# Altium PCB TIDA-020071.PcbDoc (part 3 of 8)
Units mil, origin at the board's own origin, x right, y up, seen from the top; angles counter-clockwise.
Board outline 5750 x 4050 mil, 6 copper layers (Top Layer, GND PLANE-1, SIGNAL LAYER, SIGNAL/POWER LAYER, GND PLANE-2, Bottom Layer), stack 59.616 mil thick; 776 components, 498 nets, 2205 pads, 871 vias.
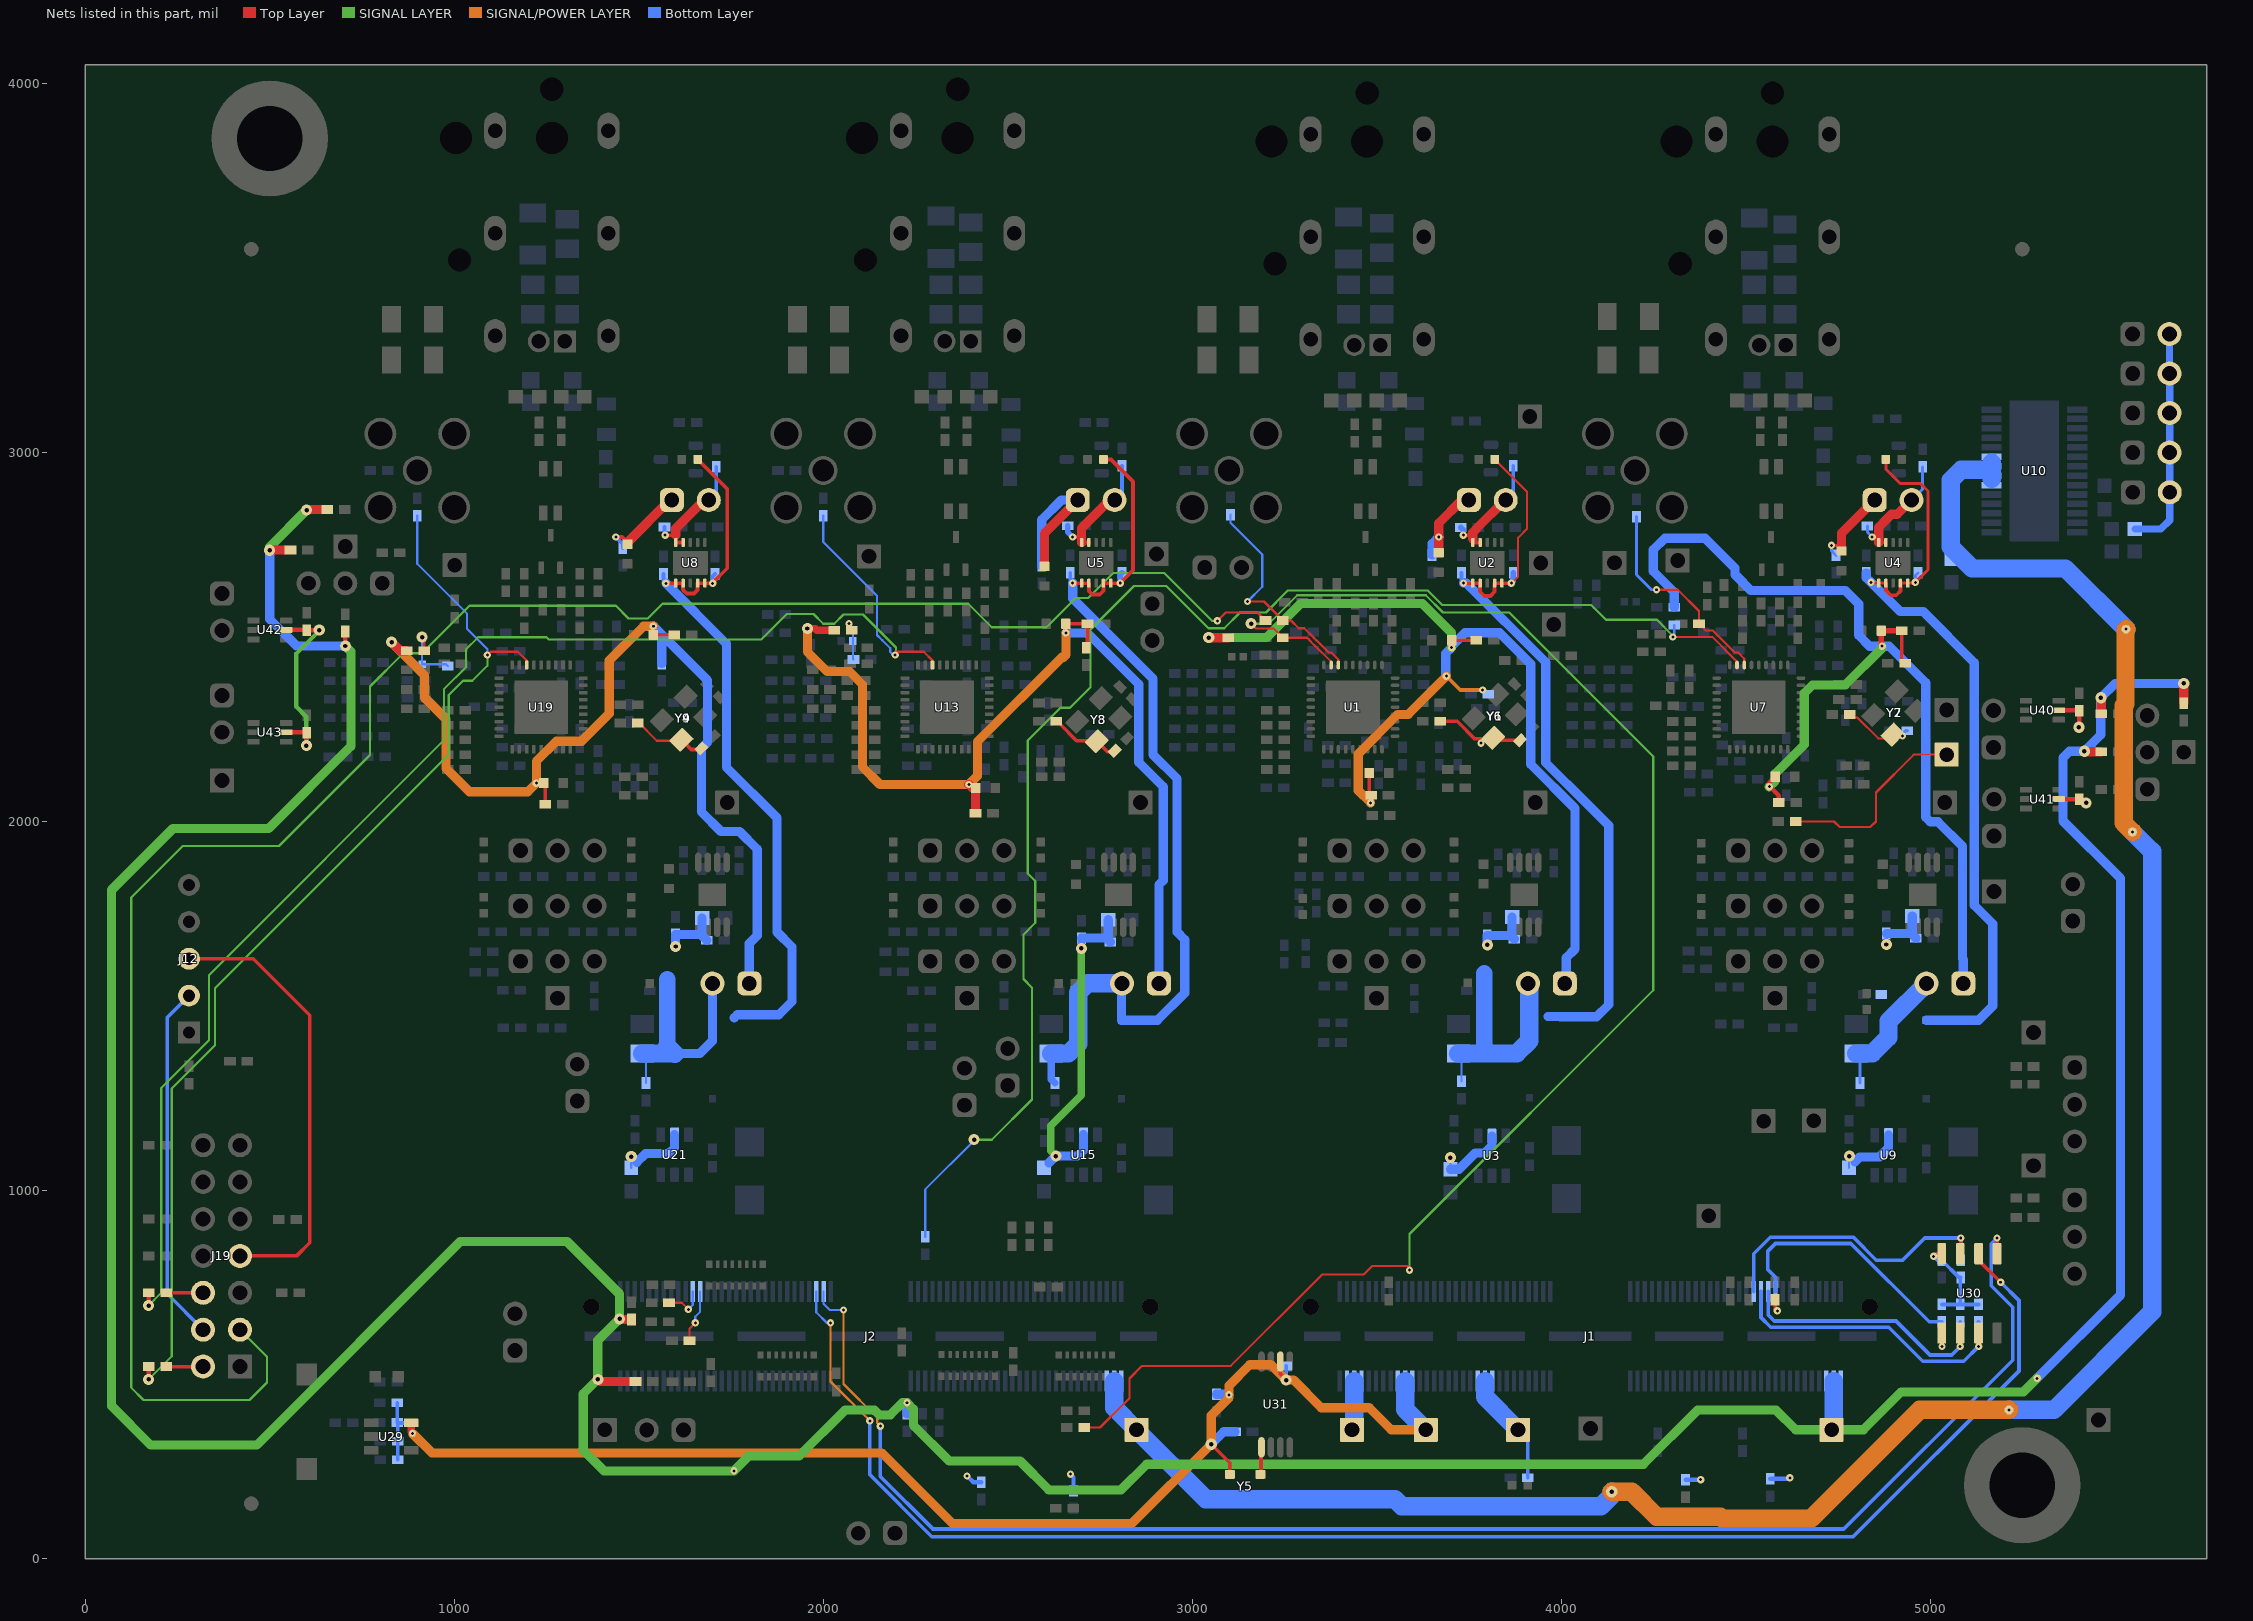
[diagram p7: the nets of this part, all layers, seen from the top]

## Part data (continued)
R11 R64 R117 R170: library part CMP-0026298-2, "RES, 33.2 k, 1%, 0.063 W, AEC-Q200 Grade 0, 0402", Manufacturer=Vishay-Dale, Power_W=63mW, Supplier Part Number 1=541-33.2KLCT-ND, TempCo="100 ppm/C", Tolerance_%=1%, Value2=0.063W, Value_Code=33k2, ValueDisplayed=33.2k
R13 R66: library part CMP-0026952-5, "RES, 5.6 k, 5%, 0.063 W, AEC-Q200 Grade 0, 0402", Manufacturer=Vishay-Dale, Power_W=63mW, Supplier Part Number 1=541-5.6KJCT-ND, TempCo="200 ppm/C", Tolerance_%=5%, Value2=0.063W, Value_Code=5k60, ValueDisplayed=5.6k
R14 R67: library part CMP-0026027-3, "RES, 15.0 k, 1%, 0.063 W, AEC-Q200 Grade 0, 0402", Manufacturer=Vishay-Dale, Power_W=63mW, Supplier Part Number 1=541-15.0KLCT-ND, TempCo="100 ppm/C", Tolerance_%=1%, Value2=0.063W, Value_Code=15k0, ValueDisplayed=15.0k
R15 R18 R19 R22 R29 R30 R31 R32 R33 R34 R35 R36 R37 R38 R68 R71 R72 R75 R82 R83 R84 R85 R86 R87 R89 R90 R91 R121 R124 R125 R128 R135 R136 R137 R138 R139 R140 R142 R143 R144 R174 R177 R178 R181 R188 R189 R190 R191 R192 R193 R194 R195 R197 R341 R342 R343 R344 R345 R346 R370 R371 R373 R374 R375 R378 R379 R381 R382 R383 R386 R387 R388 R389 R391: library part CMP-0026237-2, "RES, 2.49 k, 1%, 0.063 W, AEC-Q200 Grade 0, 0402", Manufacturer=Vishay-Dale, Power_W=63mW, Supplier Part Number 1=541-2.49KLCT-ND, TempCo="100 ppm/C", Tolerance_%=1%, Value2=0.063W, Value_Code=2k49
R16 R17 R20 R21 R23 R23-2 R25 R26 R27 R28 R48 R49 R69 R70 R73 R74 R76 R76-2 R78 R79 R80 R101 R102 R122 R123 R126 R127 R129 R129-2 R131 R132 R133 R154 R155 R175 R176 R179 R180 R182 R182-2 R184 R185 R186 R207 R208 R264 R265 R266 R267 R268 R306 R312 R315 R318 R321 R323: library part CMP-0026890-5, "RES, 2.2 k, 5%, 0.063 W, AEC-Q200 Grade 0, 0402", Manufacturer=Vishay-Dale, Power_W=63mW, Supplier Part Number 1=541-2.2KJCT-ND, TempCo="200 ppm/C", Tolerance_%=5%, Value2=0.063W, Value_Code=2k20, ValueDisplayed=2k2
R23-1 R76-1 R129-1 R182-1 R275 R276 R277 R278 R307 R309 R310 R313: library part CMP-0025958-1, "RES, 10.0 k, 1%, 0.063 W, 0402", Manufacturer=Vishay-Dale, Power_W=63mW, Supplier Part Number 1=541-10.0KLCT-ND, TempCo="100 ppm/C", Tolerance_%=1%, Value2=0.063W, Value_Code=10k0, ValueDisplayed=10.0k
R24 R77 R81 R111 R114 R115 R130 R134 R151 R164 R217 R271 R272 R273 R274 R280 R282 R330 R331 R332 R333 R340 R347 R348 R361 R365 R367 R376 R400 R404 R408 R409 R410 R411 R412 R413 R414 R415 R416 R417 R418: library part CMP-0026992-3, "RES, 0, 5%, 0.1 W, AEC-Q200 Grade 0, 0402", Manufacturer=Panasonic, Power_W=100mW, Supplier Part Number 1=P0.0JCT-ND, TempCo="600 ppm/C", Tolerance_%=5%, Value2=0.1W, Value_Code=0000, ValueDisplayed=0
R58: library part CMP-0026992-3, "RES, 0, 5%, 0.1 W, AEC-Q200 Grade 0, 0402", Manufacturer=Panasonic, Power_W=100mW, Supplier Part Number 1=P0.0JCT-ND, TempCo="600 ppm/C", Tolerance_%=5%, Value2=0.1W, Value_Code=0000
R59 R112 R165 R218: library part CMP-0025951-3, "RES, 100, 1%, 0.063 W, AEC-Q200 Grade 0, 0402", Manufacturer=Vishay-Dale, Power_W=63mW, Supplier Part Number 1=541-100LCT-ND, TempCo="100 ppm/C", Tolerance_%=1%, Value2=0.063W, Value_Code=100R, ValueDisplayed=100
R60 R61 R113 R166 R167 R219: library part CMP-0026071-3, "RES, 1.00 k, 1%, 0.063 W, AEC-Q200 Grade 0, 0402", Manufacturer=Vishay-Dale, Power_W=63mW, Supplier Part Number 1=541-1.00KLCT-ND, TempCo="100 ppm/C", Tolerance_%=1%, Value2=0.063W, Value_Code=1k00, ValueDisplayed=1k0
R88 R196 R372 R390: library part CMP-0078669-1, "RES, 10.0 k, 1%, 0.063 W, 0402", Manufacturer="Yageo America", Power_W=63mW, Supplier Part Number 1=311-10.0KLRCT-ND, TempCo="100 ppm/C", Tolerance_%=1%, Value2=0.063W, Value_Code=10k0, ValueDisplayed=10k
R98 R269 R308 R311 R324: library part CMP-0026816-1, "RES, 2.00 k, 0.1%, 0.063 W, 0402", Manufacturer="Susumu Co Ltd", Power_W=63mW, Supplier Part Number 1=RG10P2.0KBCT-ND, TempCo="25 ppm/C", Tolerance_%=0.1%, Value2=0.063W, Value_Code=2k00, ValueDisplayed=2k0
R119 R172: library part CMP-0026076-3, "RES, 1.13 k, 1%, 0.063 W, AEC-Q200 Grade 0, 0402", Manufacturer=Vishay-Dale, Power_W=63mW, Supplier Part Number 1=541-1.13KLCT-ND, TempCo="100 ppm/C", Tolerance_%=1%, Value2=0.063W, Value_Code=1k13, ValueDisplayed=1.13k
R120 R173: library part CMP-0026410-2, "RES, 4.53 k, 1%, 0.063 W, AEC-Q200 Grade 0, 0402", Manufacturer=Vishay-Dale, Power_W=63mW, Supplier Part Number 1=541-4.53KLCT-ND, TempCo="100 ppm/C", Tolerance_%=1%, Value2=0.063W, Value_Code=4k53, ValueDisplayed=4.53k
R141: library part CMP-0026739-1, "RES, 4.70 k, 1%, 0.0625 W, 0402", Manufacturer="Yageo America", Power_W=62.5mW, Supplier Part Number 1=311-4.7KLRCT-ND, TempCo="100 ppm/C", Tolerance_%=1%, Value2=0.0625W, Value_Code=4k70, ValueDisplayed=4k7
R168 R183 R187 R204: library part CMP-0089632-1, "0 Ohms Jumper 0.125W, 1/8W Chip Resistor 0805 (2012 Metric) Automotive AEC-Q200 Thick Film", Digikey Part Number=RMCF0805ZT0R00CT-ND, Manufacturer="Stackpole Electronics", Operating Temperature Range="-55°C to +155°C", Power_W=125mW, TempCo=200ppm/°C
R220 R229: library part CMP-0021998-4, "RES, 10.0 k, 1%, 0.1 W, AEC-Q200 Grade 0, 0603", Manufacturer=Vishay-Dale, Power_W=100mW, Supplier Part Number 1=541-10.0KHCT-ND, TempCo="100 ppm/C", Tolerance_%=1%, Value2=0.1W, Value_Code=10k0, ValueDisplayed=10.0k
R223 R224 R234 R235 R245 R246 R253 R254: library part CMP-0026210-2, "RES, 26.7, 1%, 0.063 W, AEC-Q200 Grade 0, 0402", Manufacturer=Vishay-Dale, Power_W=63mW, Supplier Part Number 1=541-26.7LCT-ND, TempCo="100 ppm/C", Tolerance_%=1%, Value2=0.063W, Value_Code=26R7
R225 R226 R236 R237 R247 R248 R255 R256: library part CMP-0021848-2, "RES, 1.00 k, 1%, 0.25 W, 0805", Manufacturer=Panasonic, Power_W=250mW, Supplier Part Number 1=P16058CT-ND, TempCo="100 ppm/C", Tolerance_%=1%, Value2=0.25W, Value_Code=1k00, ValueDisplayed=1k0
R227 R238 R249 R257: library part CMP-0020834-3, "RES, 100 k, 1%, 0.125 W, AEC-Q200 Grade 0, 0805", Manufacturer=Vishay-Dale, Power_W=125mW, Supplier Part Number 1=541-100KCCT-ND, TempCo="100 ppm/C", Tolerance_%=1%, Value2=0.125W, Value_Code=100k
R228 R239 R250 R258: library part CMP-0018610-3, "RES, 1.0 M, 5%, 0.25 W, AEC-Q200 Grade 0, 1206", Manufacturer=Vishay-Dale, Power_W=250mW, Supplier Part Number 1=541-1.0MECT-ND, TempCo="200 ppm/C", Tolerance_%=5%, Value2=0.25W, Value_Code=1M00, ValueDisplayed=1M
R230: library part CMP-0025797-4, "RES, 3.3 k, 5%, 0.1 W, AEC-Q200 Grade 0, 0603", Manufacturer=Vishay-Dale, Power_W=100mW, Supplier Part Number 1=541-3.3KGCT-ND, TempCo="200 ppm/C", Tolerance_%=5%, Value2=0.1W, Value_Code=3k30, ValueDisplayed=3.3k
R259: library part CMP-0074667-1, "RES, 2.20 k, 0.1%, 0.0625 W, AEC-Q200 Grade 0, 0402", Manufacturer=Panasonic, Power_W=62.5mW, Supplier Part Number 1=P2.2KDCCT-ND, TempCo="25 ppm/C", Tolerance_%=0.1%, Value2=0.0625W, Value_Code=2k20, ValueDisplayed=2k2
R260: library part CMP-0026660-1, "RES, 1.00 M, 1%, 0.1 W, 0402", Manufacturer=Panasonic, Power_W=100mW, Supplier Part Number 1=P1.00MLCT-ND, TempCo="100 ppm/C", Tolerance_%=1%, Value2=0.1W, Value_Code=1M00, ValueDisplayed=1M
R262: library part CMP-0026736-1, "RES, 470, 1%, 0.063 W, 0402", Manufacturer="Yageo America", Power_W=63mW, Supplier Part Number 1=311-470LRCT-ND, TempCo="100 ppm/C", Tolerance_%=1%, Value2=0.063W, Value_Code=470R, ValueDisplayed=470
R279 R281: library part CMP-0026992-3, "RES, 10.0 k, 1%, 0.1 W, 0402", Manufacturer=Panasonic, PartNumber=ERJ-2GE0R00X, Power_W=100mW, Supplier Part Number 1=P0.0JCT-ND, TempCo="600 ppm/C", Tolerance_%=5%, Value2=0.1W, Value_Code=0000, ValueDisplayed=10k
R380: library part CMP-0026237-2, "RES, 2.49 k, 1%, 0.063 W, AEC-Q200 Grade 0, 0402", Manufacturer=Vishay-Dale, Power_W=63mW, Supplier Part Number 1=541-2.49KLCT-ND, TempCo="100 ppm/C", Tolerance_%=1%, Value2=0.063W, Value_Code=2k49, ValueDisplayed=2.49k
RN1 RN2 RN3 RN4: library part CMP-0015352-2, "RES, 0, 5%, 0.0625 W, Resistor Array - 8x1", Manufacturer=Panasonic, Power_W=62.5mW, Supplier Part Number 1=Y1000CT-ND, TempCo=ppm/C, Tolerance_%=5%, Value2=0.0625W, Value_Code=0000, ValueDisplayed=0
S1: library part CMP-0002170-2, "Switch, Normally open, 2.3N force, 200k operations, SMD", CurrentRating_mA=1.001kA, Manufacturer="C&K Components"
U1 U7: library part CMP-0085268-1, "Low Power Auto PHY 1000BASE-T1 Automotive Ethernet Physical Layer Transceiver, RND0036A (VQFNP-36)", Alternate Manufacturer="Texas Instruments", Alternate PartNumber=DP83TG720SWRNDTQ1, PartNumber=DP83TG721-Q1
U2 U4 U5 U8: library part CMP-0036364-1, "Single Output Automotive LDO, 500 mA, Adjustable 0.8 to 3.6 V Output, 0.8 to 5.5 V Input, with Programmable Soft Start, 10-pin SON (DRC), -40 to 125 degC, Green (RoHS & no Sb/Br)", Manufacturer="Texas Instruments", Rating=Automotive
U3 U9 U15 U21: library part CMP-0076377-2, "SIMPLE SWITCHER(R) 4.5V to 42V, 0.6A Step-Down DC/DC Switching Regulator in SOT-23 Package, DDC0006A (SOT-23-T-6)", Alternate Manufacturer="Texas Instruments", Alternate PartNumber=LMR14206XMKE/NOPB
U6 U12 U18 U24: library part CMP-0013312-4, "300mA High-Voltage Ultra-Low-Iq Low-Dropout (LDO) Regulator, DGN0008D (VSSOP-8)", Alternate Manufacturer="Texas Instruments"
U10: library part CMP-0073696-3, "40-V/160-mohm Quad Channels Smart High-Side Switch, PWP0028C (TSSOP-28)", Alternate Manufacturer="Texas Instruments"
U13 U19: library part CMP-0089064-1, "TC-10 Compliant 100Base-T1 Automotive Ethernet PHY", Manufacturer="Texas Instruments", Operating Temperature Range="-40°C to +125°C", PartNumber=DP83TC818-Q1
U25 U26 U27 U28: library part CMP-0073595-1, "Automotive Dual-Channel High-Speed ESD Protection Device, DCK0003A (SOT-SC70-3)", Alternate Manufacturer="Texas Instruments"
U29: library part CMP-0074267-1, "Nanopower Supervisory Circuits for Automotive, DBV0005A (SOT-23-5)", Alternate Manufacturer="Texas Instruments"
U30: library part CMP-0005313-2, "256 kb I2C CMOS Serial EEPROM, SOIC-8", Manufacturer="ON Semiconductor", Supplier Part Number 1=CAT24C256WI-GT3OSCT-ND
U31: library part CMP-0860874-2, "3.3-V and 2.5-V LVCMOS High-Performance Clock Buffer Family, PW0008A (TSSOP-8)", Alternate Manufacturer="Texas Instruments", Alternate PartNumber=LMK1C1104PWR
U40 U41 U42 U43: library part CMP-0860319-1, "1-ch, 2:1 general-purpose analog multiplexer with 1.8-V logic control, DCK0006A (SOT-SC70-6)", Alternate Manufacturer="Texas Instruments", Operating Temperature Range="-40 to 125 C", Rating=Catalog
Y1 Y2 Y3 Y4: library part CMP-0004682-5, "Crystal, 25 MHz, 12pF, AEC-Q200 Grade 1, SMD", Frequency_Fixed=25MHz, Frequency Stability="50 ppm", Load Capacitance="12 pF", Manufacturer="Abracon Corporation"
Y5 Y6 Y7 Y8 Y9: library part CMP-0001498-1, "Low Jitter, Low Power, LVCMOS Output, BAW Oscillator", Frequency Stability=20ppm, Frequency_Fixed=25MHz, Manufacturer="Texas Instruments", Max Supply Current=5mA, Max Supply Voltage=3.63V, Min Supply Voltage=1.62V, Operating Temperature Range="-40°C to +125°C"
ZZ1: library part CMP-0003616-3
ZZ2: library part CMP-0077236-1
ZZ3: library part CMP-0077237-1
ZZ4: library part CMP-0077238-1

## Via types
v1: diameter 20, hole 8, Top Layer to Bottom Layer, tented both sides, 637 vias
v2: diameter 30, hole 12, Top Layer to Bottom Layer, tented both sides, 105 vias
v3: diameter 19.68, hole 7.87, Top Layer to Bottom Layer, tented bottom, 68 vias
v4: diameter 19.68, hole 7.87, Top Layer to Bottom Layer, 25 vias
v5: diameter 24, hole 8, Top Layer to Bottom Layer, tented both sides, 24 vias
v6: diameter 19.68, hole 7.87, Top Layer to Bottom Layer, tented both sides, 12 vias

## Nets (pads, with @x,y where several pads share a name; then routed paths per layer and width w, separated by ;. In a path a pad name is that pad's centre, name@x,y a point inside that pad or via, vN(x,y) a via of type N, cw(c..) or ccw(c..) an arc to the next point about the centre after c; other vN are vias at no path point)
1V8: 1V8.1 J1.114 J1.116 J1.118 | length 134.5
  Bottom Layer w50: 1V8.1@3433.27,350 3439.37,356.1 J1.116@3439.37,482.01
3V3: 3V3.1 J1.2 J1.4 J1.6 R98.1 R268.2 R306.1 R308.2 R309.1 R311.2 R312.2 R313.1 R324.1 | length 12482.3
  Top Layer w12: v2(705,2474.38) R98.1@705,2513.65
  Top Layer w25: v2(499.95,2733.98) 500.61,2734.65 R311.2@556.32,2734.65 ; v2@599.37,2842.31 601.24,2844.17 R313.1@655.75,2844.17 ; v2(1389.35,487) 1395.06,481.28 R312.2@1491.38,481.28 ; v2(1448.2,650.9) 1450.17,648.93 R268.2@1480.68,648.93 ; v2(5418.35,2189.14) 5419.69,2187.79 R324.1@5464.24,2187.79 ; v2(5462.86,2334.14) 5464.24,2332.76 R308.2@5464.24,2290.63 ; R309.1@5687.51,2319.63 v2(5687.51,2372.91)
  SIGNAL LAYER w25: v2(499.95,2733.98) 499.95,2742.88 v2(599.97,2842.91) ; v2(705,2474.38) 720,2459.38 720,2202.84 497.06,1979.9 238.14,1979.9 71.41,1813.17 71.41,414.93 177.63,308.71 464.53,308.71 1016.52,860.7 1305.72,860.7 1448.2,718.22 v2(1448.2,650.9) 1389.35,592.05 v2(1389.35,487) 1350,447.65 1350,295 1406.18,238.82 v1(1758.27,238.82) 1799.07,279.62 1935.43,279.62 2059.8,404 2138.94,404 2152.44,390.5 2182.22,390.5 2215.22,423.5 v1(2227.24,423.5) 2244.51,406.24 2244.51,362.85 2341.95,265.41 2533.66,265.41 2611.71,187.36 2807.43,187.36 2877.07,257.01 4223.1,257.01 4369.65,403.55 4582.57,403.55 4636.12,350 3V3.1@4733.27,350 4819.29,350 4922.19,452.9 5253.16,452.9 v1(5290,489.74)
  Bottom Layer w25: v2(499.95,2733.98) 499.95,2547.36 572.92,2474.38 v2(705,2474.38) ; R306.1@2227.24,393.62 v1(2227.24,423.5) ; v1(5290,489.74) 5515.89,715.62 5515.89,1844.61 5360.3,2000.2 5360.3,2171.34 5378.1,2189.14 v2(5418.35,2189.14) 5462.86,2233.65 v2(5462.86,2334.14) 5501.64,2372.91 v2(5687.51,2372.91)
  Bottom Layer w50: 3V3.1@4733.27,350 4738.58,355.31 J1.4@4738.58,482.01
3V3IO: 3V3IO.1 C175.1 C177.1 C178.1 J1.100 J1.102 J1.104 R259.2 R260.1 R262.2 R269.2 U29.5 U31.6 Y5.4 | length 3877.3
  Top Layer w10: v2(3051.77,311.04) 3102.22,260.59 Y5.4@3102.22,229.29 ; U31.6@3239.2,534.99 3239.2,500.8 v2(3255,485)
  Top Layer w20: U29.5@883.27,369.16 883.27,344.17 v1(887.1,340.34)
  SIGNAL/POWER LAYER w25: v1(887.1,340.34) 939.82,287.62 2159.09,287.62 2350.25,96.45 2837.19,96.45 v2(3051.77,311.04) 3051.77,388.73 3100,436.96 v1(3100,445) 3100,469.78 3099.89,469.89 3156.31,526.31 3213.69,526.31 v2(3255,485) 3275,485 3350,410 3479.8,410 3539.8,350 3V3IO.1@3633.27,350
  Bottom Layer w10: R262.2@845.87,423.09 R260.1@845.87,369.76 R260.1@847.24,368.39 ; R259.2@847.24,269.09 C175.1@847.24,319.09 R260.1@847.24,368.39 ; v1(887.1,340.34) 887.1,359.8 878.51,368.39 R260.1@847.24,368.39 ; v2(3255,485) 3255.24,484.76 C177.1@3255.24,523.03
  Bottom Layer w25: v2(3051.77,311.04) 3085.73,345 R269.2@3116.38,345 ; C178.1@3066.15,446.72 3098.28,446.72 v1(3100,445)
  Bottom Layer w50: J1.102@3577.17,482.01 3577.17,406.1 3V3IO.1@3633.27,350
5V0: 5V0.1 C2.1 C25.1 C26.1 C36.1 C59.1 C60.1 C70.1 C93.1 C94.1 C104.1 C127.1 C128.1 C176.2 C200.2 C201.2 C202.2 C203.2 J1.78 J1.80 J1.82 J25.2 J26.2 J27.2 J33.2 J34.2 R10.2 R28.2 R44.2 R63.2 R97.2 R116.2 R150.2 R169.2 R203.2 R229.1 R264.2 R265.2 R266.2 R267.2 U3.5 U9.5 U15.5 U21.5 U30.8 U40.2 U41.2 U42.2 U43.2 | length 4083.2
  Top Layer w10: v2@4880,1663.78 v2(4881.61,1665.39) ; v1(5009.85,820) 5017.17,827.32 U30.8@5031.5,827.32
  Top Layer w12: U43.2@544.74,2240.5 599.33,2240.5 C203.2@600.45,2239.39 599.33,2238.28 v2(599.33,2204.6) ; U42.2@544.74,2517.9 599.86,2517.9 C202.2@600.45,2517.31 v2(634.32,2517.31) ; U41.2@5348.69,2059.49 5403.81,2059.49 C201.2@5404.4,2058.9 5413.1,2058.9 v2(5422.9,2049.1) ; U40.2@5348.69,2300.42 5403.28,2300.42 C200.2@5404.4,2299.31 5404.4,2255.19 v2(5403.35,2254.14)
  SIGNAL LAYER w12: v2(599.33,2204.6) 599.33,2282.7 572.45,2309.59 572.45,2454.08 635,2516.63 v2(634.32,2517.31)
  SIGNAL LAYER w20: v2(2630.6,1092.11) 2617,1105.71 2617,1174.3 2700,1257.3 v2(2700,1655.01)
  Bottom Layer w6: v2(1479.83,1090.5) 1480,1090.33 C104.1@1480,1060 ; C2.1@3700,1056.42 3700,1087.64 v2(3700.06,1087.7) ; C36.1@4780,1060 4780,1090.93 v2(4781.18,1092.11)
  Bottom Layer w10: v1(2670.54,230) 2678.58,221.95 R116.2@2678.58,184.86 ; 5V0.1@3883.27,350 3910,323.27 R28.2@3910,220 ; v2(4881.61,1665.39) R97.2@4881.61,1695.16 ; v1(5009.85,820) 5019.85,810 C176.2@5031.5,810 5078.74,762.76 R267.2@5083.11,762.76 5081.5,761.14 R265.2@5081.5,690 ; R264.2@5031.5,690 R265.2@5081.5,690 ; R266.2@5131.5,690 R265.2@5081.5,690
  Bottom Layer w12: v1(2390,225) 2406.52,208.48 R169.2@2428.58,208.48 ; R10.2@4337.29,215 4378.03,215 v1(4378.11,214.93) ; R63.2@4566.73,217.76 4617.76,217.76 v1(4620,220)
  Bottom Layer w20: v2(2700,1655.01) R150.2@2700,1682.76 ; R229.1@5555.32,2791.5 5625.63,2791.5 5649.62,2815.49 J34.2@5649.62,2890.97 5649.39,2891.19 5649.39,3212.49 J26.2@5649.17,3212.72 5648.94,3212.94 5648.94,3320.11 J25.2@5648.71,3320.34
  Bottom Layer w25: C104.1@1495.17,1075.16 1518.77,1098.77 1581.95,1098.77 1597.4,1114.23 U21.5@1597.4,1150 ; v2(1600.13,1660) 1600.13,1667.03 1600,1667.16 R203.2@1600,1692.76 1668.95,1692.76 1671.79,1689.92 ; C128.1@1671.79,1737.16 1671.79,1689.92 ; C127.1@1684.54,1677.16 1671.79,1689.92 ; C70.1@2611.96,1073.47 v2(2630.6,1092.11) 2690.12,1092.11 2705.89,1107.89 U15.5@2705.89,1150 ; R150.2@2700,1682.76 2767.8,1682.76 C93.1@2772.52,1678.03 ; C94.1@2772.52,1732.28 C93.1@2772.52,1678.03 ; C93.1@2778.27,1672.28 C93.1@2772.52,1678.03 ; C2.1@3700,1056.42 3723.21,1056.42 3767.32,1100.52 3793.7,1100.52 3812.6,1119.42 U3.5@3812.6,1146.64 ; v2(3800,1664.41) R44.2@3800,1690 3862.76,1690 C25.1@3867.01,1685.75 ; C26.1@3867.01,1740 C25.1@3867.01,1685.75 ; C25.1@3872.76,1680 C25.1@3867.01,1685.75 ; C36.1@4796.65,1076.65 4809.53,1089.53 4862.83,1089.53 4887.4,1114.09 U9.5@4887.4,1148.27 ; R97.2@4881.61,1695.16 4948.86,1695.16 C59.1@4951.61,1692.4 ; C60.1@4951.61,1742.4 C59.1@4951.61,1692.4 ; C59.1@4961.61,1682.4 C59.1@4951.61,1692.4
  Bottom Layer w50: J1.80@3793.7,482.01 3793.7,439.57 5V0.1@3883.27,350
12V0: 12V0.1 C103.1 J2.2 J2.4 J2.6 U10.20 U10.21 U10.22 U10.23 | length 6063.5
  SIGNAL/POWER LAYER w50: v2(4137.32,182.24) 4191.59,182.24 4259.6,114.24 4431.87,114.24 4436.3,109.81 4678.06,109.81 4972.25,404 v5(5214.01,404) ; v5(5531.44,2519.9) 5529.7,2518.16 5529.7,2318.25 5524.38,2312.93 5524.38,2159.51 5525.1,2158.79 5525.1,2123.16 5524.38,2122.44 5524.38,1995.03 v5(5549.03,1970.38)
  Bottom Layer w50: J2.4@2788.58,482.01 2788.58,410 2789.32,410 12V0.1@2849.32,350 3037.49,161.83 3549.9,161.83 3568.61,143.11 4108.03,143.11 4137.32,172.4 v2(4137.32,182.24) ; 5150.19,2952.66 5084.88,2952.66 5055.59,2923.37 5055.59,2743.37 5114.54,2684.42 5366.92,2684.42 v5(5531.44,2519.9) ; 5166.69,2927.3 U10.21@5166.69,2936.16 5166.69,2952.89 U10.22@5166.69,2961.75 5166.69,2970.61 ; v5(5214.01,404) 5335.59,404 5601.72,670.13 5601.72,1917.69 v5(5549.03,1970.38)
"721/725 Enable/1": R314.2 R354.1 U1.17 | length 4341.9
  Top Layer w6: R354.1@2707.88,356.1 2750.47,356.1 2830,435.63 2830,489.38 2864.02,523.41 3104.91,523.41 3352.6,771.1 3465.52,771.1 3488.86,794.44 3586.9,794.44 3589.1,792.23 v1(3589.1,782.92) ; v2(3160,2535) 3173.09,2521.91 3221.14,2521.91 R314.2@3246.04,2497.01 3311.53,2497.01 3315.9,2492.64 3315.9,2492.03 3331.13,2476.8 3331.74,2476.8 3376.77,2431.77 U1.17@3376.77,2422.91
  SIGNAL LAYER w6: v2(3160,2535) 3207.8,2535 3284.8,2612 3633.38,2612 3679.93,2565.45 3859.36,2565.45 4250,2174.81 4250,1541.5 3589.1,880.6 v1(3589.1,782.92)
"721/725 Enable/2": R317.2 R362.2 U7.17 | length 3930.9
  Top Layer w6: v1(4302.72,2498.79) 4305.19,2498.79 4306.53,2497.45 4308.29,2499.2 4409.34,2499.2 4476.77,2431.77 U7.17@4476.77,2422.91
  SIGNAL LAYER w6: v2(2409.36,1136.41) 2457.21,1136.41 2566.2,1245.4 2566.2,1548.4 2542.8,1571.8 2542.8,1691.8 2575,1724 2575,1837.3 2554.5,1857.8 2554.5,2218.28 2643.22,2307 2668.99,2307 2724.57,2362.58 2724.57,2519.14 2842.23,2636.8 2929.9,2636.8 3044.2,2522.5 3087.05,2522.5 3130,2565.45 3200,2565.45 3259.55,2625 3638.77,2625 3678.27,2585.5 4081.68,2585.5 4121.74,2545.45 4259.7,2545.45 4302.72,2502.43 v1(4302.72,2498.79)
  Bottom Layer w6: R362.2@2276.77,873.62 2276.77,1001.77 2409.36,1134.36 v2(2409.36,1136.41) ; v1(4302.72,2498.79) 4303.02,2498.49 4306.66,2498.49 R317.2@4306.66,2531.62
"721/725 Enable/3": C320.1 R320.1 R321.2 | length 102
  Bottom Layer w6: v1(2070,2535) 2080.75,2524.25 C320.1@2080.75,2488 2080.75,2439.32 R320.1@2082.1,2437.97
"721/725 Enable/4": C322.1 R322.1 R323.2 | length 184.2
  Top Layer w6: v2(912.99,2498.38) 918.62,2492.75 R323.2@918.62,2461.69
  Bottom Layer w6: v2(912.99,2498.38) C322.1@912.99,2425 977.76,2425 R322.1@982.76,2420
+1V0-3: C75.1 J44.1 L17.1 | length 461.3
  Top Layer w25: L17.1@2600,2690.16 2600,2780 J44.1@2690,2870
  Bottom Layer w25: C75.1@2592.54,2692.13 2592.54,2816.78 2645.76,2870 J44.1@2690,2870
+1V0-4: C109.1 J59.1 L18.1 | length 242.9
  Top Layer w10: v1(1438.38,2770) 1454.8,2770 L18.1@1469.69,2755.12
  Top Layer w25: L18.1@1469.69,2755.12 1584.57,2870 J59.1@1590,2870
  Bottom Layer w10: v1(1438.38,2770) 1456.51,2751.87 C109.1@1456.51,2740
+1V0_REG-3: J44.2 R119.2 R132.2 U5.9 U5.10 | length 355.7
  Top Layer w10: v1(2676.38,2770) 2700,2770 2700.63,2770 U5.10@2700.63,2755.12 U5.9@2720.31,2755.12
  Top Layer w25: U5.10@2700.63,2755.12 2700,2755.75 2700,2770 2700,2793.31 2776.69,2870 J44.2@2790,2870
  Bottom Layer w10: J44.2@2790,2870 2810,2890 R132.2@2810,2962.76
  Bottom Layer w15: R119.2@2662.76,2800 2662.76,2783.62 v1(2676.38,2770)
+1V0_REG-4: J59.2 R172.2 R185.2 U8.9 U8.10 | length 328.5
  Top Layer w10: v1(1571.82,2775) 1600.63,2775 U8.10@1600.63,2755.12 U8.9@1620.31,2755.12
  Top Layer w25: 1600.63,2775 1600.63,2792.85 1677.78,2870 J59.2@1690,2870
  Bottom Layer w10: R172.2@1569.86,2796.89 1569.86,2776.96 v1(1571.82,2775) ; J59.2@1690,2870 1710,2890 R185.2@1710,2960
+1V1-1: C7.1 J14.1 L11.1 | length 243.7
  Top Layer w25: L11.1@3668.38,2727.53 v1(3668.38,2770) 3668.38,2807.1 3731.27,2870 J14.1@3750,2870
  Bottom Layer w25: C7.1@3650.35,2721.02 3650.35,2751.98 v1(3668.38,2770)
+1V1-2: C41.1 J29.1 L14.1 | length 235.8
  Top Layer w8: v1(4732.8,2747.4) 4758.19,2747.4 4760,2745.59 L14.1@4760,2731.9
  Top Layer w25: 4760,2745.59 4760,2780 J29.1@4850,2870
  Bottom Layer w8: v1(4732.8,2747.4) 4732.8,2732.33 C41.1@4745.13,2720
+1V1_REG-1: J14.2 R13.2 R26.2 U2.9 U2.10 | length 326.6
  Top Layer w10: v1(3735.04,2775) 3750.89,2775 3760.63,2765.26 U2.10@3760.63,2755.12 U2.9@3780.31,2755.12
  Top Layer w25: U2.10@3760.63,2765.26 3760.63,2781.69 3770.5,2791.56 3770.5,2792.22 3848.28,2870 J14.2@3850,2870
  Bottom Layer w10: J14.2@3850,2870 3870,2890 R26.2@3870,2962.76
  Bottom Layer w15: R13.2@3728.35,2795.57 3735.04,2788.88 v1(3735.04,2775)
+1V1_REG-2: J29.2 R66.2 R79.2 U4.9 U4.10 | length 342.3
  Top Layer w8: v1(4842.9,2770) 4857.78,2755.12 U4.10@4860.63,2755.12 U4.9@4880.31,2755.12
  Top Layer w25: U4.10@4860.63,2755.12 4860.63,2796.5 4881.28,2817.15 4881.41,2817.15 4895.52,2831.26 4911.26,2831.26 J29.2@4950,2870
  Bottom Layer w8: R66.2@4830.08,2799.76 4830.08,2782.82 v1(4842.9,2770) ; J29.2@4950,2870 4980,2900 R79.2@4980,2960
+3V3-1: C8.1 C9.1 J13.1 L9.1 L10.1 R24.1 R315.1 | length 2859.2
  Top Layer w10: L9.1@3480,2130 3480,2075.12 C9.1@3485.12,2070 3485.12,2050.88 v1(3483.74,2049.5) ; v1(3703.15,2470) L10.1@3703.15,2490 C8.1@3770,2490
  Top Layer w25: v2(3045,2497.24) 3045.24,2497.01 R315.1@3097.68,2497.01
  Top Layer w50: J13.1@4009.47,1559.47 J13.1@4010,1560
  SIGNAL LAYER w25: v2(3045,2497.24) 3201.87,2497.24 3294.12,2589.5 3624.06,2589.5 3703.15,2510.41 v1(3703.15,2470)
  SIGNAL/POWER LAYER w10: v1(3689.1,2392.57) 3726.45,2355.22 v1(3787.27,2355.22)
  SIGNAL/POWER LAYER w25: v1(3483.74,2049.5) 3450.25,2082.99 3450.25,2181.72 3557.59,2289.05 3585.59,2289.05 v1(3689.1,2392.57)
  Bottom Layer w25: v1(3689.1,2392.57) 3687.5,2394.17 3687.5,2454.35 v1(3703.15,2470) 3703.15,2473.99 3739.66,2510.5 3832.85,2510.5 3917.49,2425.86 3917.49,2153.91 4037.6,2033.8 4037.6,1653.08 4014.12,1629.6 4014.12,1564.12 J13.1@4010,1560
+3V3-2: C42.1 C43.1 J28.1 L12.1 L13.1 R81.1 R318.1 | length 2865.4
  Top Layer w10: C42.1@4923.31,2515.78 4923.31,2434.8 4930.12,2427.99 R81.1@4932.63,2427.99
  Top Layer w12: L12.1@4580,2120 4564.38,2104.38 v1(4564.38,2093.12) 4566,2093.12 4590,2069.12 C43.1@4590,2050
  Top Layer w15: v1(4870,2473.97) 4867.87,2476.1 L13.1@4867.87,2515.78 C42.1@4923.31,2515.78
  Top Layer w25: J28.1@5086.58,1556.58 J28.1@5090,1560
  SIGNAL LAYER w25: v1(4564.38,2093.12) 4580,2108.74 4580,2128.19 4658.99,2207.17 4658.99,2346.38 4681.71,2369.1 4770.24,2369.1 4870,2468.86 v1(4870,2473.97)
  Bottom Layer w25: R318.1@4306.66,2579.57 4306.66,2620.46 4250,2677.12 4250,2735.24 4281.41,2766.65 4390.17,2766.65 4471.23,2685.59 4471.23,2668.06 4514.29,2625 4770,2625 4806.61,2588.39 4806.61,2503.34 4835.99,2473.97 v1(4870,2473.97) 4889.03,2473.97 4988.02,2374.98 4988.02,2010.58 5000.58,1998.02 5021.13,1998.02 5087.69,1931.46 5087.69,1626.69 5090.28,1624.09 5090,1623.81 J28.1@5090,1560
+3V3-3: C76.1 C77.1 J43.1 L15.1 L16.1 R115.1 R321.1 | length 2710
  Top Layer w10: v1@2658,2507.09 v1(2658,2510) L16.1@2658,2534.62 C76.1@2716.33,2534.62 R115.1@2716.33,2476.66
  Top Layer w20: v2(1957.28,2521.81) 1978.19,2521.81 1982.56,2517.44 R321.1@2030.1,2517.44
  Top Layer w25: v1(2394.88,2099.17) 2404.05,2090 L15.1@2413.43,2090 2412.96,2089.53 C77.1@2412.96,2021.5
  SIGNAL/POWER LAYER w25: v2(1957.28,2521.81) 1957.28,2458.71 2011,2405 2071.69,2405 2106.3,2370.38 2106.3,2147.04 2154.17,2099.17 v1(2394.88,2099.17) 2417.97,2122.25 2417.97,2214.69 2647.24,2443.96 2651.25,2443.96 2658,2450.72 v1(2658,2510)
  Bottom Layer w25: v1(2658,2510) 2715.72,2510 2855.12,2370.6 2855.12,2159.51 2921.75,2092.88 2921.75,1838.97 2910,1827.22 J43.1@2910,1560
+3V3-4: C110.1 C111.1 J58.1 L19.1 L20.1 R134.1 R323.1 | length 2724.3
  Top Layer w6: J58.1@1800,1560 J58.1@1802.57,1557.43
  Top Layer w10: v1(1222.79,2102.76) L20.1@1242.47,2102.76 1247.17,2098.06 C111.1@1247.17,2045.2 ; v1(1540,2528) L19.1@1540,2504.62 C110.1@1596.2,2504.62
  Top Layer w25: v2(830.28,2485) 853.58,2461.69 R323.1@871.38,2461.69
  SIGNAL/POWER LAYER w25: v2(830.28,2485) 919.68,2395.6 919.68,2335 978.05,2276.62 978.05,2143.16 1041.74,2079.47 1199.5,2079.47 v1(1222.79,2102.76) 1222.79,2161.84 1277.35,2216.41 1345.11,2216.41 1420.37,2291.66 1420.37,2435 1513.37,2528 v1(1540,2528)
  Bottom Layer w25: v1(1540,2528) 1562.35,2505.65 ; R134.1@1562.35,2427.02 1562.35,2505.65 ; J58.1@1800,1560 1800,1668.29 1821.63,1689.92 1821.63,1923.37 1773.11,1971.89 1723.11,1971.89 1670,2025 1670,2196.63 1686.78,2213.41 1686.78,2381.22 1562.35,2505.65
+3V3_REG-1: C4.1 C5.1 C6.1 D4.2 J13.2 L5.2 R11.2 R27.2 U2.1 U2.2 U2.4 U2.5 | length 2788.3
  Top Layer w6: D4.2@3820,2980 3907.47,2892.52 3907.47,2791.93 3883.54,2767.99 3883.54,2663.07 v1(3865.35,2644.88)
  Top Layer w10: v1(3735.62,2644.88) U2.1@3760.63,2644.88 U2.2@3780.31,2644.88 3780.31,2621.46 3791.78,2610 3808.46,2610 3819.69,2621.23 U2.4@3819.69,2644.88 U2.5@3839.37,2644.88 v1(3865.35,2644.88)
  Bottom Layer w6: C4.1@3721.65,1370 3730,1361.65 R11.2@3730,1294.76
  Bottom Layer w10: C5.1@3730,2672.76 3730,2650.5 v1(3735.62,2644.88)
  Bottom Layer w15: v1(3865.35,2644.88) 3870,2649.53 C6.1@3870,2672.76
  Bottom Layer w25: v1(3735.62,2644.88) 3743.72,2644.88 3958.29,2430.32 3958.29,2158.37 4070,2046.65 4128.9,1987.75 4128.9,1502.58 4095.99,1469.67 3998,1469.67 3997.38,1470.29 3964.59,1470.29
  Bottom Layer w45: 3791.77,1383.85 R27.2@3791.77,1540 3791.77,1586.7
  Bottom Layer w50: C4.1@3721.65,1370 3805.62,1370 ; 3791.77,1383.85 3805.62,1370 ; J13.2@3910,1560 3914.25,1555.75 L5.2@3914.25,1462.6 3914.25,1404.75 3879.49,1370 3805.62,1370
+3V3_REG-2: C38.1 C39.1 C40.1 D12.2 J28.2 L6.2 R64.2 R80.2 U4.1 U4.2 U4.4 U4.5 | length 2555
  Top Layer w8: v1(4840,2646.93) 4842.05,2644.88 U4.1@4860.63,2644.88 U4.2@4880.31,2644.88 ; D12.2@4880,2980 4880,2954.49 4920.13,2914.35 4974.62,2914.35 4994.35,2894.62 4994.35,2681.28 v1(4960,2646.93) 4957.95,2644.88 U4.5@4939.37,2644.88 U4.4@4919.69,2644.88
  Top Layer w10: U4.2@4880.31,2644.88 4880.31,2624.57 4893.1,2611.78 4908.26,2611.78 4919.69,2623.2 U4.4@4919.69,2644.88
  Bottom Layer w8: C38.1@4800,1370 4810,1360 R64.2@4810,1290 ; v1(4960,2646.93) 4960,2665.2 C39.1@4967.32,2672.52
  Bottom Layer w25: C40.1@4827.32,2672.52 4827.32,2659.61 v1(4840,2646.93) 4919.17,2567.75 4981.25,2567.75 5119.69,2429.31 5119.69,1771.56 5170,1721.26 5170,1498.7 5131.3,1460 L6.2@4990,1460
  Bottom Layer w50: C38.1@4800,1370 4842.75,1370 4887.4,1414.65 4887.4,1457.4 J28.2@4990,1560
+3V3_REG-3: C72.1 C73.1 C74.1 D20.2 J43.2 L7.2 R117.2 R133.2 U5.1 U5.2 U5.4 U5.5 | length 2608.7
  Top Layer w10: v1(2676.38,2644.88) U5.1@2700.63,2644.88 U5.2@2720.31,2644.88 2720.31,2623.1 2729.27,2614.14 2749.66,2614.14 2759.68,2624.16 U5.4@2759.68,2644.88 U5.5@2779.37,2644.88 v1(2805.16,2644.88) 2840,2679.72 2840,2920 2780,2980 D20.2@2760,2980
  Bottom Layer w10: C74.1@2670,2672.76 2670,2651.26 v1(2676.38,2644.88)
  Bottom Layer w15: v1(2805.16,2644.88) 2805.16,2667.91 C73.1@2810,2672.76
  Bottom Layer w20: C72.1@2618.49,1370 2618.49,1300 R117.2@2628.49,1290
  Bottom Layer w25: v1(2676.38,2644.88) 2676.38,2603.03 2893.76,2385.65 2893.76,2179.98 2959.37,2114.37 2959.37,1699.18 2980,1678.55 2980,1534.06 2905.94,1460 L7.2@2808.49,1460 2808.49,1558.49 J43.2@2810,1560
  Bottom Layer w50: C72.1@2618.49,1370 2664.99,1370 2690.87,1395.88 2690.87,1534.16 2716.71,1560 J43.2@2810,1560
+3V3_REG-4: C106.1 C107.1 C108.1 D28.2 J58.2 L8.2 R170.2 R186.2 U8.1 U8.2 U8.4 U8.5 | length 2716.3
  Top Layer w10: v1(1573.92,2644.38) 1574.43,2644.88 U8.1@1600.63,2644.88 U8.2@1620.31,2644.88 1620.31,2626.5 1630.28,2616.53 1650.23,2616.53 1659.68,2625.99 U8.4@1659.68,2644.88 U8.5@1679.37,2644.88 1699.89,2644.88 1740,2684.99 1740,2900 D28.2@1660,2980
  Bottom Layer w6: C106.1@1510,1370 1520,1360 R170.2@1520,1290
  Bottom Layer w10: C107.1@1567.11,2669.65 1567.11,2651.2 v1(1573.92,2644.38) ; v1(1700.39,2644.38) 1700.39,2662.93 C108.1@1707.11,2669.65
  Bottom Layer w25: v1(1573.92,2644.38) 1737.8,2480.5 1737.8,2146.05 1875,2008.85 1875,1699.15 1915.26,1658.89 1915.26,1510.66 1879.37,1474.76 1766.94,1474.76 1759.09,1466.92 ; 1597.4,1369 1597.4,1370 1665.78,1370 1700,1404.22 L8.2@1700,1460 J58.2@1700,1560
  Bottom Layer w45: 1577.24,1389.16 R186.2@1577.24,1540 1577.24,1571
  Bottom Layer w50: C106.1@1510,1370 1596.4,1370 ; 1577.24,1389.16 1596.4,1370 ; 1597.4,1369 1596.4,1370
BAW_CLK_OUT: U31.1 Y5.3 | length 74.7
  Top Layer w10: Y5.3@3184.89,229.29 3186.54,230.94 3186.54,301.23 U31.1@3188.02,302.7
BAW_NC1: C32.1 R60.1 Y1.1 Y6.1 | length 250.5
  Top Layer w10: R60.1@3672.24,2270.55 3672.62,2270.18 3718.27,2270.18 3765.77,2222.68 3782.78,2222.68 ; v1(3782.78,2211.05) 3794.41,2222.68 Y6.1@3813.37,2222.68 ; Y6.1@3813.02,2231.89 3814.39,2233.26 3824.02,2233.26 3838.16,2219.11 3873.81,2219.11 3876.59,2216.33 3886.23,2216.33 C32.1@3889.01,2219.11
BAW_NC2: C66.1 R113.1 Y2.1 Y7.1 | length 210.5
  Top Layer w6: R113.1@4781.81,2288.5 4789.42,2280.89 4802.49,2280.89 4859.27,2224.11 4877.66,2224.11 4879.04,2222.73 4905.42,2222.73 Y2.1@4908.2,2225.51
  Top Layer w10: Y7.1@4896.95,2241.48 4898.34,2242.87 4907.97,2242.87 4909.37,2241.48 4911.8,2241.48 4922.51,2230.76 v1(4925.21,2230.76)
  Bottom Layer w10: v1(4925.21,2230.76) 4925.21,2233.47 4927.36,2235.62 4927.36,2238.19 4934.17,2245 C66.1@4938.11,2245
BAW_NC3: C100.1 R166.1 Y3.1 Y8.1 | length 194.4
  Top Layer w10: R166.1@2632.09,2270.11 2636.02,2270.11 2642.83,2263.29 2642.83,2262.05 2686.93,2217.95 2740.09,2217.95 Y3.1@2741.68,2216.37 2770.33,2187.71 2787.71,2187.71 C100.1@2790.5,2190.5
BAW_NC4: C134.1 R219.1 Y4.1 Y9.1 | length 205.8
  Top Layer w6: R219.1@1497.44,2265.55 1501.38,2265.55 1549.27,2217.66 1613.16,2217.66 Y4.1@1615.94,2220.44
  Top Layer w10: Y4.1@1615.94,2220.44 1642.46,2193.93 1667.3,2193.93 C134.1@1670.08,2196.71
BC_Main: J12.3 J19.7 | length 1210.9
  Top Layer w10: J12.3@281.23,1626.78 455.31,1626.78 608.42,1473.66 608.42,1143.56 608.42,857.05 572.81,821.45 J19.7@419.53,821.45
CC_Main: J12.2 J19.4 | length 970.1
  Bottom Layer w10: J12.2@281.23,1526.78 222.24,1467.78 222.24,718.75 J19.4@319.53,621.45
CLKOUT-1: R58.1 R333.1 U1.16 | length 614
  Top Layer w6: v1(3150,2595) 3194.77,2595 R333.1@3246.04,2543.72 3267.88,2543.72 3288.85,2522.76 3304.17,2522.76 3328.9,2498.02 3328.9,2497.41 3336.52,2489.8 3337.12,2489.8 3370.39,2456.53 3377.35,2456.53 3396.46,2437.42 U1.16@3396.46,2422.91
  Bottom Layer w6: R58.1@3104.13,2830.12 3104.13,2808.46 3190.15,2722.45 3190.15,2635.15 v1(3150,2595)
CLKOUT-1-TP: J19.3 R333.2 | length 5603.5
  Top Layer w6: v1(3068.58,2542.52) 3091.51,2565.45 3177.07,2565.45 R333.2@3198.8,2543.72
  SIGNAL LAYER w6: J19.3@419.53,621.45 492.5,548.48 492.5,478.5 445.1,431.1 158.2,431.1 124.8,464.5 124.8,1793 264.3,1932.5 525.3,1932.5 771.61,2178.81 771.61,2364.8 861.81,2455 912.9,2455 1041.3,2583.4 1438.38,2583.4 1472.56,2549.22 1525,2549.22 1564.82,2589.03 2393.27,2589.03 2457.18,2525.12 2605.12,2525.12 2684.19,2604.19 2717.95,2604.19 2785.97,2672.21 2924.19,2672.21 3053.88,2542.52 v1(3068.58,2542.52)
CLKOUT-2: R111.1 R408.1 U7.16 | length 581.3
  Top Layer w6: v1(4258.5,2626.9) 4316.11,2626.9 4373.62,2569.39 R408.1@4373.62,2534.62 4392.04,2516.2 4410.72,2516.2 4470.39,2456.53 4479.9,2456.53 4496.46,2439.97 U7.16@4496.46,2422.91
  Bottom Layer w8: R111.1@4204.13,2825 4204.13,2667.77 4245,2626.9 v1(4258.5,2626.9)
CLKOUT-3: R164.1 R413.1 U13.16 | length 4051.6
  Top Layer w6: v1(2195,2450) 2195,2455 2199.09,2459.09 2272.56,2459.09 2296.46,2435.2 U13.16@2296.46,2422.91
  Top Layer w12: v2(171.91,686.89) R413.1@171.91,721.45
  SIGNAL LAYER w6: v2(171.91,686.89) 206.3,721.28 206.3,1139.7 206.3,1276.6 335.3,1405.6 335.3,1582.27 972.11,2219.08 972.11,2357.21 1032,2417.1 1032,2465.36 1065.01,2498.38 1249.97,2498.38 1256.18,2492.17 1832.17,2492.17 1901.41,2561.41 1973.71,2561.41 2000.12,2535 2030,2535 2055,2560 2108.18,2560 2197.63,2470.55 2197.63,2452.63 v1(2195,2450)
  Bottom Layer w6: R164.1@2000,2827.76 2000,2756.3 2145.67,2610.63 2145.67,2504.49 2160,2490.16 2181.88,2468.28 2181.88,2458.12 2190,2450 v1(2195,2450)
CLKOUT-3-TP: J19.6 R413.2 | length 100.4
  Top Layer w10: R413.2@219.16,721.45 J19.6@319.53,721.45
CLKOUT-4: R217.1 R418.1 U19.16 | length 2981.7
  Top Layer w6: v1(1090,2450) 1099.09,2459.09 1172.56,2459.09 1196.46,2435.2 U19.16@1196.46,2422.91
  Top Layer w12: v2(171.91,486.89) R418.1@171.91,521.45
  SIGNAL LAYER w6: v2(171.91,486.89) 234.5,549.48 234.5,1275 351.8,1392.3 351.8,1546.97 985.21,2180.38 985.21,2341.35 1023.86,2380 1049.22,2380 1090,2420.78 v1(1090,2450)
  Bottom Layer w6: R217.1@900,2827.76 900,2697.23 1034.42,2562.81 1034.42,2522.08 1090,2466.5 v1(1090,2450)
CLKOUT-4-TP: J19.2 R418.2 | length 100.4
  Top Layer w10: R418.2@219.16,521.45 J19.2@319.53,521.45
EE-A0: J1.19 R264.1 U30.1 | length 752.6
  Bottom Layer w10: J1.19@4581.1,725 4581.1,763.54 4560.5,784.14 4560.5,834.59 4580.9,855 4785.36,855 4997.61,642.76 R264.1@5031.5,642.76 5031.5,576.71 v1(5032.26,575.94)
EE-A1: J1.21 R265.1 U30.2 | length 741.7
  Top Layer w10: v1(5081.5,575.94) U30.2@5081.5,612.76
  Bottom Layer w10: J1.21@4561.42,725 4561.42,661.42 4577.73,645.1 4907.83,645.1 4999.94,553 5058.56,553 v1(5081.5,575.94) R265.1@5081.5,642.76
EE-A2: J1.23 R266.1 U30.3 | length 829.5
  Top Layer w10: v1(5131.5,575.94) U30.3@5131.5,612.76
  Bottom Layer w10: J1.23@4541.73,725 4541.73,654.51 4568.14,628.1 4887.9,628.1 4980,536 5091.56,536 v1(5131.5,575.94) R266.1@5131.5,642.76
EE-SCL: J2.65 U30.6 | length 4296.4
  Top Layer w10: U30.6@5131.5,827.32 5131.5,809.92 v1(5191.42,750)
  SIGNAL/POWER LAYER w6: v1(2020.07,639.79) 2020.07,481.15 v1(2126.72,374.5)
  Bottom Layer w6: J2.65@1981.5,725 1981.5,668.5 2010.2,639.79 v1(2020.07,639.79) v1@2020.87,639.79
  Bottom Layer w10: v1(2126.72,374.5) 2126.72,228.1 2294.6,60.22 4791.4,60.22 5240.8,509.62 5240.8,700.62 v1(5191.42,750)
EE-SDA: J2.63 U30.5 | length 4308.3
  Top Layer w10: U30.5@5181.5,827.32 v1(5181.5,870)
  SIGNAL/POWER LAYER w6: v1(2055,675) 2055,474.5 2146.72,382.79 2146.72,368.28 v1(2155,360)
  Bottom Layer w6: J2.63@2001.18,725 2001.18,691.69 2017.87,675 v1(2055,675)
  Bottom Layer w10: v1(2155,360) 2155,223.86 2297.4,81.45 4766.34,81.45 5223.8,538.91 5223.8,682.59 5165.64,740.75 5165.64,854.14 v1(5181.5,870)
EE-WP: J1.25 R267.1 U30.7 | length 835.6
  Top Layer w10: U30.7@5081.5,827.32 5083.11,828.94 v1(5083.11,870)
  Bottom Layer w10: J1.25@4522.05,725 4522.05,827.05 4567,872 4792.41,872 4854.41,810 4925.28,810 4985.28,870 v1(5083.11,870) R267.1@5083.11,810
ENA: R4.2 | length 32.8
  Top Layer w10: R4.2@4580,702.76 4580,678.64 v1(4586.13,672.51)
EventCapture2: LED_0_2.1 R331.2 | length 542.8
  Top Layer w6: R331.2@4635.85,1998.96 4739.69,1998.96 4754.95,1983.7 4838.08,1983.7 4853.33,1998.96 4853.33,2077.53 4955.81,2180 LED_0_2.1@5045,2180
GESI_MDIO0_MDC: J2.97 R300.1 | length 145.2
  Top Layer w6: R300.1@1637.72,591.7 1637.72,624.26 v1(1653.46,640)
  Bottom Layer w6: v1(1653.46,640) 1653.46,656.64 1666.54,669.72 J2.97@1666.54,725
GESI_MDIO0_MDIO: J2.99 R301.1 | length 113.5
  Top Layer w6: R301.1@1582.24,694.49 1616.8,694.49 v1(1634.8,676.49)
  Bottom Layer w6: v1(1634.8,676.49) 1646.85,688.54 J2.99@1646.85,725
